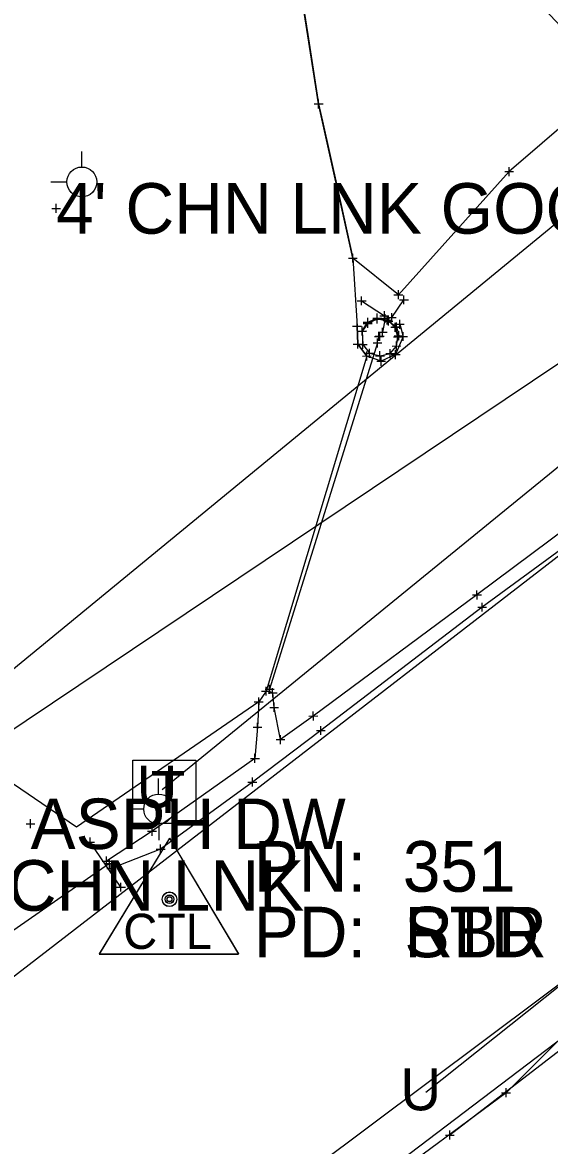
# Model space of a CAD drawing. Extents: x -1 to 1157254, y -1 to 2021979.
# Drawn here: x 1149805.7 to 1149880.9, y 2019249.4 to 2019409.5 of the extents above; entities that cross this region are included whole.
import ezdxf

# ---------------------------------------------------------------- set-up
doc = ezdxf.new("R2010")
doc.units = 0
for name, color, linetype in [('S_AREA_CALC', 7, 'Continuous'), ('S_BUILDING_ANNOT', 7, 'Continuous'), ('S_CAL_CORNER_ANNOT', 7, 'Continuous'), ('S_CATCH_BASIN', 7, 'Continuous'), ('S_CATCH_BASIN_ANNOT', 7, 'Continuous'), ('S_CONTOUR_ANNOT', 7, 'Continuous'), ('S_CONTOUR_MAJOR', 7, 'Continuous'), ('S_CONTOUR_MINOR', 7, 'Continuous'), ('S_CTL_TABLE', 7, 'Continuous'), ('S_DITCHLINE', 7, 'Continuous'), ('S_DRIVEWAY_ANNOT', 7, 'Continuous'), ('S_DROP_INLET', 7, 'Continuous'), ('S_DROP_INLET_ANNOT', 7, 'Continuous'), ('S_EDGE_BITUMINOUS_ANNOT', 7, 'Continuous'), ('S_ELECTRIC_UTILITIES', 7, 'Continuous'), ('S_ELECTRIC_UTILITIES_ANNOT', 7, 'Continuous'), ('S_FENCE', 7, 'Continuous'), ('S_GAS_PUMP_ISLAND_ANNOT', 7, 'Continuous'), ('S_GAS_UTILITIES', 7, 'Continuous'), ('S_GATE', 7, 'Continuous')]:
    doc.layers.add(name, color=color, linetype=linetype)

msp = doc.modelspace()

# ---------------------------------------------------------------- linework, layer by layer
at = {"layer": 'S_AREA_CALC'}
for p, q in [((1149826.7, 2019293.21), (1149816.67, 2019276.7)), ((1149826.71, 2019293.23), (1149816.68, 2019276.72)), ((1149826.7, 2019293.21), (1149836.52, 2019276.7)), ((1149826.71, 2019293.23), (1149836.53, 2019276.72)), ((1149816.67, 2019276.7), (1149836.52, 2019276.7)), ((1149816.68, 2019276.72), (1149836.53, 2019276.72))]:
    msp.add_line(p, q, dxfattribs=at)
for centre, radius in [((1149826.7, 2019284.51), 1.04), ((1149826.71, 2019284.53), 1.04), ((1149826.71, 2019284.53), 0.609), ((1149826.7, 2019284.51), 0.609), ((1149826.7, 2019284.51), 0.344), ((1149826.71, 2019284.53), 0.344)]:
    msp.add_circle(centre, radius, dxfattribs=at)
at = {"layer": 'S_BUILDING_ANNOT'}
for p, q in [((1149847.33, 2019397.87), (1149848.61, 2019397.87)), ((1149847.97, 2019397.24), (1149847.97, 2019398.51)), ((1149847.97, 2019397.87), (1149847.97, 2019397.87)), ((1149874.49, 2019388.23), (1149875.77, 2019388.23)), ((1149875.13, 2019387.59), (1149875.13, 2019388.87)), ((1149875.13, 2019388.23), (1149875.13, 2019388.23)), ((1149809.92, 2019382.98), (1149811.19, 2019382.98)), ((1149810.55, 2019382.34), (1149810.55, 2019383.62)), ((1149810.55, 2019382.98), (1149810.55, 2019382.98)), ((1149852.85, 2019375.25), (1149852.84, 2019376.52)), ((1149852.21, 2019375.88), (1149853.48, 2019375.89)), ((1149852.85, 2019375.88), (1149852.85, 2019375.88)), ((1149854.1, 2019369.17), (1149854.1, 2019370.44)), ((1149858.7, 2019370.68), (1149859.97, 2019370.68)), ((1149859.34, 2019370.04), (1149859.33, 2019371.32)), ((1149859.33, 2019370.68), (1149859.33, 2019370.68)), ((1149859.5, 2019369.94), (1149860.77, 2019369.94)), ((1149860.13, 2019369.31), (1149860.13, 2019370.58)), ((1149860.13, 2019369.94), (1149860.13, 2019369.94)), ((1149853.47, 2019369.8), (1149854.74, 2019369.8)), ((1149854.1, 2019369.8), (1149854.1, 2019369.8)), ((1149857.34, 2019367.06), (1149857.34, 2019368.33)), ((1149854.97, 2019365.94), (1149854.97, 2019367.22)), ((1149855.68, 2019367.21), (1149856.95, 2019367.21)), ((1149856.31, 2019366.58), (1149856.31, 2019367.85)), ((1149856.31, 2019367.21), (1149856.31, 2019367.21)), ((1149856.7, 2019367.69), (1149857.98, 2019367.69)), ((1149856.79, 2019367.29), (1149858.07, 2019367.29)), ((1149857.27, 2019366.92), (1149858.54, 2019366.92)), ((1149857.34, 2019367.69), (1149857.34, 2019367.69)), ((1149857.43, 2019366.65), (1149857.43, 2019367.92)), ((1149857.43, 2019367.29), (1149857.43, 2019367.29)), ((1149857.76, 2019367.43), (1149859.03, 2019367.43)), ((1149857.91, 2019366.29), (1149857.91, 2019367.56)), ((1149857.91, 2019366.92), (1149857.91, 2019366.92)), ((1149858.4, 2019366.79), (1149858.39, 2019368.07)), ((1149858.4, 2019367.43), (1149858.4, 2019367.43)), ((1149858.89, 2019365.41), (1149858.89, 2019366.69)), ((1149853.53, 2019365.49), (1149854.8, 2019365.49)), ((1149854.17, 2019364.85), (1149854.17, 2019366.13)), ((1149854.17, 2019365.49), (1149854.17, 2019365.49)), ((1149854.33, 2019366.58), (1149855.61, 2019366.58)), ((1149854.97, 2019366.58), (1149854.97, 2019366.58)), ((1149856.45, 2019365.33), (1149857.72, 2019365.33)), ((1149856.56, 2019364.1), (1149856.56, 2019365.37)), ((1149856.68, 2019364.12), (1149856.68, 2019365.39)), ((1149857.08, 2019364.69), (1149857.08, 2019365.96)), ((1149857.08, 2019365.33), (1149857.08, 2019365.33)), ((1149858.26, 2019366.05), (1149859.53, 2019366.05)), ((1149858.89, 2019366.05), (1149858.89, 2019366.05)), ((1149859.28, 2019364.05), (1149859.28, 2019365.33)), ((1149853.63, 2019363.59), (1149854.9, 2019363.6)), ((1149854.26, 2019362.96), (1149854.26, 2019364.23)), ((1149854.26, 2019363.59), (1149854.26, 2019363.59)), ((1149855.72, 2019363.81), (1149856.99, 2019363.81)), ((1149855.93, 2019364.73), (1149857.2, 2019364.74)), ((1149856.04, 2019364.76), (1149857.31, 2019364.76)), ((1149856.36, 2019363.17), (1149856.35, 2019364.45)), ((1149856.36, 2019363.81), (1149856.36, 2019363.81)), ((1149856.56, 2019364.74), (1149856.56, 2019364.74)), ((1149856.68, 2019364.76), (1149856.68, 2019364.76)), ((1149858.65, 2019364.69), (1149859.92, 2019364.69)), ((1149859.07, 2019362.74), (1149859.06, 2019364.01)), ((1149859.28, 2019364.69), (1149859.28, 2019364.69)), ((1149854.6, 2019362.33), (1149855.87, 2019362.33)), ((1149855.24, 2019361.7), (1149855.24, 2019362.97)), ((1149855.24, 2019362.33), (1149855.24, 2019362.33)), ((1149856.08, 2019361.98), (1149857.35, 2019361.98)), ((1149856.72, 2019361.34), (1149856.71, 2019362.62)), ((1149856.72, 2019361.98), (1149856.72, 2019361.98)), ((1149857.54, 2019362.3), (1149858.81, 2019362.3)), ((1149858.18, 2019361.66), (1149858.17, 2019362.93)), ((1149858.18, 2019362.3), (1149858.18, 2019362.3)), ((1149858.43, 2019363.37), (1149859.7, 2019363.38)), ((1149859.06, 2019363.37), (1149859.06, 2019363.37)), ((1149870.55, 2019327.25), (1149870.54, 2019328.52)), ((1149869.91, 2019327.89), (1149871.18, 2019327.89)), ((1149870.54, 2019327.89), (1149870.54, 2019327.89)), ((1149871.28, 2019325.51), (1149871.28, 2019326.78)), ((1149870.65, 2019326.14), (1149871.92, 2019326.15)), ((1149871.28, 2019326.15), (1149871.28, 2019326.15)), ((1149839.84, 2019314.18), (1149841.11, 2019314.18)), ((1149840.34, 2019314.45), (1149841.61, 2019314.45)), ((1149840.47, 2019313.54), (1149840.47, 2019314.81)), ((1149840.47, 2019314.18), (1149840.47, 2019314.18)), ((1149840.78, 2019313.95), (1149842.05, 2019313.96)), ((1149840.97, 2019313.82), (1149840.97, 2019315.09)), ((1149840.97, 2019314.45), (1149840.97, 2019314.45)), ((1149841.42, 2019313.32), (1149841.41, 2019314.59)), ((1149841.42, 2019313.95), (1149841.42, 2019313.95)), ((1149838.79, 2019312.65), (1149840.06, 2019312.65)), ((1149839.43, 2019312.01), (1149839.43, 2019313.29)), ((1149839.43, 2019312.65), (1149839.43, 2019312.65)), ((1149841.62, 2019311.23), (1149841.62, 2019312.51)), ((1149840.99, 2019311.87), (1149842.26, 2019311.87)), ((1149841.62, 2019311.87), (1149841.62, 2019311.87)), ((1149846.58, 2019310.63), (1149847.85, 2019310.64)), ((1149847.22, 2019310), (1149847.21, 2019311.27)), ((1149847.21, 2019310.63), (1149847.21, 2019310.63)), ((1149838.61, 2019309.04), (1149839.88, 2019309.04)), ((1149839.25, 2019308.41), (1149839.24, 2019309.68)), ((1149839.25, 2019309.04), (1149839.25, 2019309.04)), ((1149848.28, 2019307.93), (1149848.28, 2019309.2)), ((1149842.53, 2019306.63), (1149842.52, 2019307.91)), ((1149847.65, 2019308.56), (1149848.92, 2019308.57)), ((1149848.28, 2019308.57), (1149848.28, 2019308.57)), ((1149841.89, 2019307.27), (1149843.16, 2019307.27)), ((1149842.52, 2019307.27), (1149842.52, 2019307.27)), ((1149838.26, 2019304.6), (1149839.53, 2019304.6)), ((1149838.89, 2019303.96), (1149838.89, 2019305.24)), ((1149838.89, 2019304.6), (1149838.89, 2019304.6)), ((1149837.88, 2019301.21), (1149839.15, 2019301.21)), ((1149838.52, 2019300.58), (1149838.52, 2019301.85)), ((1149838.52, 2019301.21), (1149838.52, 2019301.21)), ((1149806.26, 2019295.27), (1149807.53, 2019295.27)), ((1149806.9, 2019294.64), (1149806.9, 2019295.91)), ((1149806.9, 2019295.27), (1149806.9, 2019295.27)), ((1149824.23, 2019293.57), (1149824.22, 2019294.85)), ((1149815.38, 2019292.03), (1149815.38, 2019293.31)), ((1149823.59, 2019294.21), (1149824.86, 2019294.21)), ((1149824.22, 2019294.21), (1149824.22, 2019294.21)), ((1149814.74, 2019292.67), (1149816.02, 2019292.67)), ((1149815.38, 2019292.67), (1149815.38, 2019292.67)), ((1149824.81, 2019291.67), (1149826.08, 2019291.67)), ((1149825.44, 2019291.03), (1149825.44, 2019292.3)), ((1149825.44, 2019291.67), (1149825.44, 2019291.67)), ((1149817.09, 2019289.95), (1149818.36, 2019289.96)), ((1149817.72, 2019289.32), (1149817.72, 2019290.59)), ((1149817.72, 2019289.95), (1149817.72, 2019289.95)), ((1149818.14, 2019288.98), (1149818.13, 2019290.26)), ((1149817.5, 2019289.62), (1149818.77, 2019289.62)), ((1149817.76, 2019288.89), (1149819.03, 2019288.89)), ((1149818.13, 2019289.62), (1149818.13, 2019289.62)), ((1149818.4, 2019288.26), (1149818.4, 2019289.53)), ((1149818.4, 2019288.89), (1149818.4, 2019288.89)), ((1149819.78, 2019285.61), (1149819.77, 2019286.88)), ((1149819.14, 2019286.24), (1149820.41, 2019286.24)), ((1149819.78, 2019286.24), (1149819.78, 2019286.24)), ((1149866.68, 2019250.27), (1149866.68, 2019251.54)), ((1149866.04, 2019250.91), (1149867.31, 2019250.91)), ((1149866.68, 2019250.91), (1149866.68, 2019250.91))]:
    msp.add_line(p, q, dxfattribs=at)
at = {"layer": 'S_CAL_CORNER_ANNOT'}
msp.add_lwpolyline([(1150682.05, 2019865.85), (1150601.54, 2019813.47), (1150510.58, 2019743.97), (1150405.28, 2019665.92), (1150310.69, 2019593.56), (1150188.92, 2019499.64), (1150039.45, 2019388.15), (1149962.15, 2019331.17), (1149944.63, 2019319.08), (1149774.15, 2019191.52), (1149712.73, 2019145.6), (1149665.81, 2019108.74), (1149605.46, 2019057.66), (1149527.46, 2018983.58), (1149450.12, 2018902.93), (1149278.32, 2018738.82), (1149257.2, 2018716.38), (1149237.23, 2018691.25), (1149165.09, 2018617.77), (1149125.26, 2018579.57), (1149069.5, 2018523.84), (1149012.03, 2018473.77), (1148938.88, 2018408.55)], dxfattribs=at)
at = {"layer": 'S_CATCH_BASIN'}
for p, q in [((1149814.21, 2019388.86), (1149814.21, 2019391.1)), ((1149812.11, 2019386.72), (1149809.79, 2019386.72)), ((1149814.28, 2019382.31), (1149814.28, 2019384.63)), ((1149825.15, 2019299.49), (1149825.15, 2019301.73)), ((1149823.06, 2019297.36), (1149820.74, 2019297.36)), ((1149825.23, 2019292.94), (1149825.23, 2019295.27))]:
    msp.add_line(p, q, dxfattribs=at)
for centre in [(1149814.21, 2019386.75), (1149825.16, 2019297.38)]:
    msp.add_circle(centre, 2.13, dxfattribs=at)
at = {"layer": 'S_CATCH_BASIN_ANNOT'}
msp.add_lwpolyline([(1149821.47, 2019295.32), (1149821.47, 2019304.32), (1149830.47, 2019304.32), (1149830.47, 2019295.32)], close=True, dxfattribs=at)
at = {"layer": 'S_CONTOUR_ANNOT'}
for points in [[(1150857.08, 2020031.73), (1150832.22, 2020016.43), (1150747.37, 2019963.08), (1150692.94, 2019929.63), (1150639.49, 2019893), (1150583.9, 2019856.96), (1150484.25, 2019790.85), (1150433.08, 2019750.74), (1150355.8, 2019695.65), (1150341.28, 2019681.73), (1150287.94, 2019641.18), (1150216.41, 2019587.25), (1150034.4, 2019445.88), (1149979.98, 2019405.6), (1149934.92, 2019374.11), (1149784.56, 2019258.12)], [(1150776.08, 2020000.06), (1150711.77, 2019956.26), (1150627.27, 2019900.66), (1150578.77, 2019864.96), (1150479.12, 2019798.68), (1150423.47, 2019764.16), (1150358.5, 2019722.73), (1150313.96, 2019690.01), (1150273.95, 2019661.03), (1150225.64, 2019623.26), (1150033.5, 2019468.9), (1149971.69, 2019423.78), (1149931.59, 2019393.98), (1149688.42, 2019230.92)]]:
    msp.add_lwpolyline(points, dxfattribs=at)
at = {"layer": 'S_CONTOUR_MINOR'}
msp.add_lwpolyline([(1149889.62, 2019387.25), (1149496.68, 2019064.62)], dxfattribs=at)
at = {"layer": 'S_CTL_TABLE'}
for p, q in [((1149853.45, 2019365.59), (1149853.45, 2019366.86)), ((1149854.32, 2019366.75), (1149855.6, 2019366.75)), ((1149854.96, 2019366.11), (1149854.96, 2019367.38)), ((1149854.96, 2019366.75), (1149854.96, 2019366.75)), ((1149855.69, 2019367.36), (1149856.96, 2019367.36)), ((1149856.33, 2019366.72), (1149856.33, 2019368)), ((1149856.33, 2019367.36), (1149856.33, 2019367.36)), ((1149857.13, 2019367.07), (1149858.4, 2019367.07)), ((1149857.76, 2019366.43), (1149857.76, 2019367.71)), ((1149857.76, 2019367.07), (1149857.76, 2019367.07)), ((1149859.06, 2019365.44), (1149859.06, 2019366.71)), ((1149859.54, 2019365.83), (1149859.54, 2019367.11)), ((1149852.81, 2019366.22), (1149854.08, 2019366.22)), ((1149853.45, 2019366.22), (1149853.45, 2019366.22)), ((1149853.53, 2019365.5), (1149854.81, 2019365.51)), ((1149854.17, 2019364.87), (1149854.17, 2019366.14)), ((1149854.17, 2019365.51), (1149854.17, 2019365.51)), ((1149858.42, 2019366.08), (1149859.69, 2019366.08)), ((1149858.9, 2019366.47), (1149860.17, 2019366.47)), ((1149859.06, 2019366.08), (1149859.06, 2019366.08)), ((1149859.39, 2019364.21), (1149859.39, 2019365.48)), ((1149859.54, 2019366.47), (1149859.54, 2019366.47)), ((1149860.01, 2019364.09), (1149860, 2019365.36)), ((1149852.9, 2019363.64), (1149854.17, 2019363.65)), ((1149853.54, 2019363.01), (1149853.54, 2019364.28)), ((1149853.54, 2019363.64), (1149853.54, 2019363.64)), ((1149858.75, 2019364.84), (1149860.02, 2019364.85)), ((1149859.37, 2019364.73), (1149860.64, 2019364.73)), ((1149859.39, 2019364.85), (1149859.39, 2019364.85)), ((1149860, 2019364.73), (1149860, 2019364.73)), ((1149854.2, 2019361.94), (1149855.47, 2019361.95)), ((1149854.84, 2019361.31), (1149854.83, 2019362.58)), ((1149854.84, 2019361.94), (1149854.84, 2019361.94)), ((1149856.89, 2019360.56), (1149856.88, 2019361.83)), ((1149858.29, 2019362.15), (1149859.57, 2019362.15)), ((1149858.93, 2019361.51), (1149858.93, 2019362.79)), ((1149858.93, 2019362.15), (1149858.93, 2019362.15)), ((1149856.25, 2019361.2), (1149857.52, 2019361.2)), ((1149856.88, 2019361.2), (1149856.88, 2019361.2)), ((1149874.06, 2019256.95), (1149875.34, 2019256.95)), ((1149874.7, 2019256.31), (1149874.7, 2019257.58)), ((1149874.7, 2019256.95), (1149874.7, 2019256.95))]:
    msp.add_line(p, q, dxfattribs=at)
at = {"layer": 'S_DITCHLINE'}
for points in [[(1150340.68, 2019612.36), (1149611.97, 2019059.3)], [(1149857.43, 2019367.29), (1149857.08, 2019365.33)], [(1149856.36, 2019363.81), (1149840.97, 2019314.45)]]:
    msp.add_lwpolyline(points, dxfattribs=at)
at = {"layer": 'S_DRIVEWAY_ANNOT'}
for points in [[(1149861.94, 2019435.66), (1149872.83, 2019419.2), (1149883.23, 2019408.16), (1149892.16, 2019410.75), (1149894.83, 2019407.77), (1149889.57, 2019400.65), (1149875.13, 2019388.23), (1149859.33, 2019370.68), (1149852.85, 2019375.88), (1149847.97, 2019397.87), (1149843.62, 2019425.47)], [(1149929.07, 2019371.57), (1149926.83, 2019370.78), (1149924.87, 2019369.63), (1149920.56, 2019367.27), (1149901.87, 2019351.27), (1149870.54, 2019327.89), (1149847.21, 2019310.63), (1149842.52, 2019307.27), (1149841.62, 2019311.87), (1149841.42, 2019313.95), (1149840.47, 2019314.18), (1149839.43, 2019312.65), (1149839.25, 2019309.04), (1149838.89, 2019304.6), (1149824.22, 2019294.21), (1149817.72, 2019289.95)], [(1149929.34, 2019370), (1149927.96, 2019368.52), (1149924.04, 2019365.43), (1149903.01, 2019349.37), (1149871.28, 2019326.15), (1149848.28, 2019308.57), (1149838.52, 2019301.21), (1149825.44, 2019291.67), (1149818.4, 2019288.89)], [(1149858.4, 2019367.43), (1149860.13, 2019369.94)], [(1149854.1, 2019369.8), (1149857.34, 2019367.69)]]:
    msp.add_lwpolyline(points, dxfattribs=at)
at = {"layer": 'S_DROP_INLET'}
for points in [[(1150852.18, 2019973.05), (1150778.54, 2019928.45), (1150770.16, 2019919.18), (1150703.8, 2019877.29), (1150608.63, 2019809.12), (1150513.43, 2019739.89), (1150405.92, 2019663.65), (1150352.2, 2019622.72), (1150343.81, 2019614.74), (1150336.72, 2019606.98), (1150314.89, 2019591.84), (1150193.25, 2019498.28), (1150112.69, 2019435.49), (1150059.59, 2019406.16), (1150037.88, 2019389.79), (1149962.99, 2019329.91), (1149914.05, 2019297.4), (1149863.26, 2019256.98)], [(1150343.79, 2019722.31), (1149825.67, 2019300.1)]]:
    msp.add_lwpolyline(points, dxfattribs=at)
at = {"layer": 'S_DROP_INLET_ANNOT'}
msp.add_lwpolyline([(1149818.13, 2019289.62), (1149800.72, 2019277.52)], dxfattribs=at)
at = {"layer": 'S_EDGE_BITUMINOUS_ANNOT'}
for points in [[(1150022.94, 2019367.42), (1149964.57, 2019325.71), (1149928.47, 2019292.59), (1149899.27, 2019281.43), (1149874.7, 2019256.95), (1149856.33, 2019243.33), (1149830.41, 2019224.78), (1149802.41, 2019203), (1149780.2, 2019183.24), (1149750.6, 2019162.52), (1149713.11, 2019125.27), (1149684.98, 2019104.2), (1149645.14, 2019067.71), (1149630.42, 2019055.47)], [(1149854.17, 2019365.51), (1149854.96, 2019366.75), (1149856.33, 2019367.36), (1149857.76, 2019367.07), (1149859.06, 2019366.08), (1149859.39, 2019364.85)], [(1149859.54, 2019366.47), (1149860, 2019364.73), (1149858.93, 2019362.15), (1149856.88, 2019361.2), (1149854.84, 2019361.94), (1149853.54, 2019363.64), (1149853.45, 2019366.22)]]:
    msp.add_lwpolyline(points, dxfattribs=at)
at = {"layer": 'S_ELECTRIC_UTILITIES'}
msp.add_lwpolyline([(1149854.17, 2019365.49), (1149854.26, 2019363.59), (1149855.24, 2019362.33), (1149856.72, 2019361.98), (1149858.18, 2019362.3), (1149859.06, 2019363.37), (1149859.28, 2019364.69), (1149858.89, 2019366.05), (1149857.91, 2019366.92), (1149856.31, 2019367.21), (1149854.97, 2019366.58)], close=True, dxfattribs=at)
at = {"layer": 'S_ELECTRIC_UTILITIES_ANNOT'}
msp.add_lwpolyline([(1149819.78, 2019286.24), (1149815.38, 2019292.67)], dxfattribs=at)
at = {"layer": 'S_FENCE'}
msp.add_lwpolyline([(1150775.16, 2019913.88), (1150697.15, 2019862.05), (1150611.54, 2019805.47), (1150516.86, 2019735.37), (1150402.98, 2019659.79), (1150352.98, 2019622.15), (1150350.25, 2019606.72), (1150331.34, 2019598.55), (1150196.24, 2019490.87), (1150043.62, 2019380.11), (1149966.77, 2019324.72), (1149934.21, 2019308.48), (1149916.33, 2019289.12), (1149866.68, 2019250.91)], dxfattribs=at)
at = {"layer": 'S_GAS_PUMP_ISLAND_ANNOT'}
msp.add_lwpolyline([(1149778.14, 2019613.37), (1149817.67, 2019502.5), (1149818.67, 2019499.83), (1149822.19, 2019490.46), (1149822.78, 2019488.78), (1149826.07, 2019479.34), (1149829.36, 2019469.89), (1149832.65, 2019460.45), (1149843.62, 2019425.47), (1149844.85, 2019417.63), (1149846.41, 2019407.75), (1149847.97, 2019397.87), (1149848.52, 2019395.41), (1149850.68, 2019385.65), (1149852.85, 2019375.88), (1149853.45, 2019366.22), (1149853.54, 2019363.64), (1149854.84, 2019361.94), (1149840.47, 2019314.18), (1149839.43, 2019312.65), (1149813.43, 2019294.77), (1149777.76, 2019319.14)], dxfattribs=at)

# ---------------------------------------------------------------- texts
at = {"layer": 'S_AREA_CALC'}
for p in [(1149820.12, 2019277.44), (1149820.13, 2019277.46)]:
    msp.add_text('CTL', height=4.998, dxfattribs=at).set_placement(p)
at = {"layer": 'S_CATCH_BASIN_ANNOT'}
msp.add_text('T', height=6, dxfattribs=at).set_placement((1149824.04, 2019296.82))
at = {"layer": 'S_CONTOUR_MAJOR'}
for p in [(1149822.04, 2019297.56), (1149859.63, 2019254.44)]:
    msp.add_text('U', height=6, dxfattribs=at).set_placement(p)
at = {"layer": 'S_GAS_UTILITIES'}
for s, p in [('PN: ', (1149838.7, 2019285.59)), ('PN: ', (1149838.71, 2019285.61)), ('351', (1149859.97, 2019285.59)), ('35', (1149859.98, 2019285.61)), ('PD: ', (1149838.7, 2019276.23)), ('PD: ', (1149838.71, 2019276.25)), ('STD AHTD MON. STAMPED PN:35', (1149860.19, 2019276.25)), ('RBR ALUM CAP', (1149860.18, 2019276.23))]:
    msp.add_text(s, height=7.2, dxfattribs=at).set_placement(p)
at = {"layer": 'S_GATE'}
for s, p in [("4' CHN LNK GOOD", (1149810.55, 2019379.38)), ('ASPH DW', (1149806.9, 2019291.67)), ("4' CHN LNK", (1149793.78, 2019282.89))]:
    msp.add_text(s, height=7.2, dxfattribs=at).set_placement(p)

doc.saveas('drawing.dxf')
